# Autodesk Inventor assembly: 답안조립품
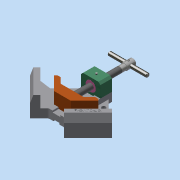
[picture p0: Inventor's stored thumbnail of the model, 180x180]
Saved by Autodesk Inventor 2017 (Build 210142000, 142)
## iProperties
Part Number: 답안조립품
Material: 일반
Document SubType Name: Assembly
Designer: 222
Author: 222
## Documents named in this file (11)
- C:\Users\222\Desktop\700506V1037\답안조립품.iam
- C:\Users\222\Desktop\700506V1037\베이스.ipt
- C:\Users\222\Desktop\700506V1037\리드스크류.ipt
- C:\Users\222\Desktop\700506V1037\멈춤나사 M4x5.ipt
- C:\Users\222\Desktop\700506V1037\멈춤나사 M4x10.ipt
- C:\Users\222\Desktop\700506V1037\볼트 M4x16.ipt
- C:\Users\222\Desktop\700506V1037\부시.ipt
- C:\Users\222\Desktop\700506V1037\서포트.ipt
- C:\Users\222\Desktop\700506V1037\조.ipt
- C:\Users\222\Desktop\700506V1037\평행 핀 2.5x24.ipt
- C:\Users\222\Desktop\700506V1037\핸들.ipt
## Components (1 placed, 1 different names)
1. 핸들:1
